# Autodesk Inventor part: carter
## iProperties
Created: 2009-09
Part Number: carter
Document SubType Name: Modeling
Designer: Olivier
Density: 1 g/cm^3
Author: Olivier
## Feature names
1. Extrusion1
2. Extrusion2
3. Extrusion3
4. Extrusion4
5. Extrusion5
6. Congé2 [Fillet]
7. Extrusion6
8. Extrusion7
9. Congé3 [Fillet]
10. Coque1
11. Extrusion8
12. Révolution1 [Revolution]
13. Chanfrein1 [Chamfer]
14. Extrusion9
